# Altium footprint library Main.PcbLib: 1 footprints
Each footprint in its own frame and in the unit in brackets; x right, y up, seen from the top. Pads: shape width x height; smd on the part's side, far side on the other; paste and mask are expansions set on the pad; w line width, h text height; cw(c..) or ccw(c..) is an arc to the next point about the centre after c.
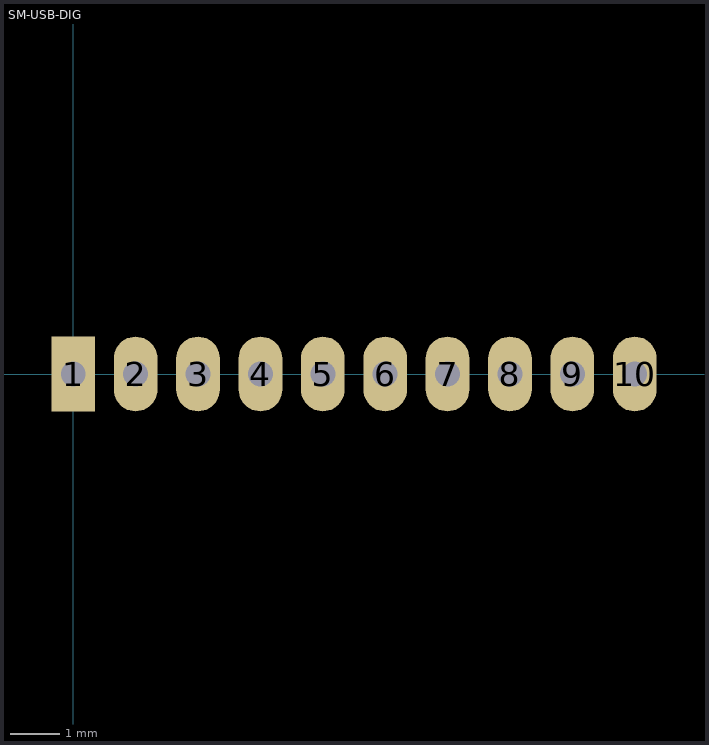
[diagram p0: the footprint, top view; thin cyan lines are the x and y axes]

## SM-USB-DIG [mil]
pads (10):
  rect 35x60 hole 20: 1(0,0)
  oval 35x60 hole 20: 2(50,0) 3(100,0) 4(150,0) 5(200,0) 6(250,0) 7(300,0) 8(350,0) 9(400,0) 10(450,0)
M5 Assembly Top:
  text ".Designator" at -60,-80 h40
